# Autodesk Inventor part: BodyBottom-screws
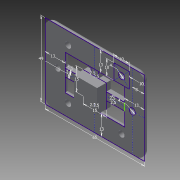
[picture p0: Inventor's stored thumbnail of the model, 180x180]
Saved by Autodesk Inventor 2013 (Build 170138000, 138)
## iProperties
Created: 2013-03
Part Number: BodyBottom-screws
Material: Generic
Document SubType Name: Modeling
Designer: frankenteddy
Density: 1 g/cm^3
Author: frankenteddy
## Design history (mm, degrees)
node "Blocks"
  sketch "Block1"
    geometry: L1 (49.279, 30.472)-(71.779, 30.472); L2 (71.779, 30.472)-(71.779, 18.072); L3 (71.779, 18.072)-(49.279, 18.072); L4 (49.279, 18.072)-(49.279, 30.472); L5 (49.279, 30.472)-(44.779, 30.472); L6 (44.779, 30.472)-(44.779, 18.072); L7 (44.779, 18.072)-(49.279, 18.072); L8 (49.279, 18.072)-(49.279, 30.472); L9 (71.779, 30.472)-(76.279, 30.472); L10 (76.279, 30.472)-(76.279, 18.072); L11 (76.279, 18.072)-(71.779, 18.072); L12 (71.779, 18.072)-(71.779, 30.472); L13 (44.779, 24.272)-(76.279, 24.272); L14 (60.529, 30.472)-(60.529, 18.072); L15 (47.029, 30.472)-(47.029, 18.072); L16 (74.029, 30.472)-(74.029, 18.072); C1 r 1.1 at (47.029, 24.272); C2 r 1.1 at (74.029, 24.272); 1 further point
    constraints: 32 end point, 8 midpoint, 6 parallel, 3 horizontal, 3 perpendicular, 2 centre point, 2 point on line
    dimensions: "d30" = 22.5 distance of L2.end L3.end; "d31" = 12.4 distance of L1.end L2.end; "d32" = 4.5 distance of L7.end L6.end; "d33" = 4.5 distance of L10.end L11.end; "d34" = 2.2 diameter of C1; "d35" = 2.2 diameter of C2; "d36" = 2.25 distance between parallel lines of L10 L16
sketch "Sketch1"
  geometry: L1 (-32.5, 24.5)-(32.5, 24.5); L2 (32.5, 24.5)-(32.5, -24.5); L3 (32.5, -24.5)-(-32.5, -24.5); L4 (-32.5, -24.5)-(-32.5, 24.5); L5 (-19.5, 11.5)-(19.5, 11.5); L6 (19.5, 11.5)-(19.5, -11.5); L7 (19.5, -11.5)-(-19.5, -11.5); L8 (-19.5, -11.5)-(-19.5, 11.5); L9 (-24.5, 24.5)-(-24.5, -24.5); L10 (-22.5, 11.5)-(-12.5, 11.5); L11 (-12.5, 11.5)-(-12.5, 21.5); L12 (-12.5, 21.5)-(-22.5, 21.5); L13 (-22.5, 21.5)-(-22.5, 11.5); L14 (-22.5, 21.5)-(-12.5, 11.5); L15 (-22.5, 11.5)-(-12.5, 21.5); L16 (32.5, 0)-(-32.5, 0); L17 (5.25, 11.5)-(-0.25, 11.5); L18 (-19.5, 2.5)-(-19.5, -2.5); L19 (5.25, -11.5)-(-0.25, -11.5); L20 (-7.5, 7.5)-(7.5, 7.5); L21 (7.5, 7.5)-(7.5, -7.5); L22 (7.5, -7.5)-(-7.5, -7.5); L23 (-7.5, -7.5)-(-7.5, 7.5); L24 (0, -7.5)-(0, 7.5); L25 (7.5, 0)-(-7.5, 0); L26 (0, 24.5)-(0, -24.5); L27 (7.5, 2.5)-(19.5, 2.5); L28 (7.5, -2.5)-(19.5, -2.5); L29 (2.5, 7.5)-(2.5, 11.5); L30 (-2.5, 7.5)-(-2.5, 11.5); L31 (-7.5, 2.5)-(-19.5, 2.5); L32 (-7.5, -2.5)-(-19.5, -2.5); L33 (-2.5, -7.5)-(-2.5, -11.5); L34 (2.5, -7.5)-(2.5, -11.5); C1 r 2 at (-24.5, 0); C2 r 2 at (-17.5, 16.5); 2 further points
  constraints: 68 end point, 17 point on line, 12 midpoint, 10 perpendicular, 9 parallel, 4 horizontal, 3 collinear, 2 centre point, 1 coincident, 1 horizontal alignment, 1 vertical alignment
  dimensions: "d0" = 65 distance of L2.end L3.end; "d1" = 49 distance of L1.end L2.end; "d2" = 13 distance between parallel lines of L5 L1; "d3" = 13 distance between parallel lines of L4 L8; "d4" = 13 distance between parallel lines of L3 L7; "d5" = 13 distance between parallel lines of L2 L6; "d11" = 8 distance between parallel lines of L9 L4; "d12" = 4 diameter of C1; "d20" = 10 distance of L12.end L11.end; "d21" = 10 distance of L11.end L10.end; "d23" = 4 diameter of C2; "d26" = 10 distance between parallel lines of L4 L13; "d71" = 15 distance of L21.end L22.end; "d72" = 15 distance of L20.end L21.end; "d73" = 2.5 distance between parallel lines of L27 L16; "d74" = 2.5 distance between parallel lines of L28 L16; "d75" = 2.5 distance between parallel lines of L26 L29; "d76" = 2.5 distance between parallel lines of L26 L30; "d77" = 2.5 distance between parallel lines of L26 L33; "d78" = 2.5 distance between parallel lines of L34 L26; "d79" = 2.5 distance between parallel lines of L16 L31; "d80" = 2.5 distance between parallel lines of L32 L16
extrude "Extrusion1" new body sketch "Sketch1" distance "d6" = 3; taper "d7" = 0 deg
extrude "Extrusion2" cut sketch "Sketch1" distance "d8" = 3; taper "d9" = 0 deg
extrude "Extrusion4" cut sketch "Sketch1" distance "d18" = 3; taper "d19" = 0 deg
mirror "Mirror1"
extrude "Extrusion5" cut sketch "Sketch1" distance "d24" = 3; taper "d25" = 0 deg
mirror "Mirror4"
mirror "Mirror5"
extrude "Extrusion14" join sketch "Sketch1" distance "d81" = 3; taper "d82" = 0 deg
fillet "Fillet1" dims "d27" = 5
fillet "Fillet2" dims "d28" = 2
fillet "Fillet4" dims "d65" = 2
extrude "Extrusion17" join sketch "Sketch1" distance "d105" = 6; taper "d106" = 0 deg
extrude "Extrusion16" join sketch "Sketch1" distance "d87" = 3; taper "d88" = 0 deg
sketch "Sketch6"
  geometry: L1 (0, 0)-(6.5, 0); L2 (0, 0)-(-6.5, 0); L3 (-6.5, 0)-(6.5, 0); L4 (6.5, 0)-(6.5, 3); L5 (6.5, 3)-(-6.5, 3); L6 (-6.5, 3)-(-6.5, 0); L7 (0, 3)-(0, 0); L8 (0, 5.75)-(0, -4.15); A1 r 4.95 centre (0, 0.8) between (0, 5.75) and (0, -4.15)
  constraints: 16 end point, 2 collinear, 2 horizontal, 2 parallel, 2 point on circle, 1 centre point, 1 midpoint, 1 perpendicular, 1 point on line
  dimensions: "d98" = 6.5 distance of L1.start L1.end; "d99" = 6.5 distance of L1.start L2.end; "d100" = 13 distance of L5.end L4.end; "d101" = 3 distance of L4.end L3.end; "d102" = 9.9 diameter of A1; "d103" = 2.2 distance from line of A1.centre L5
revolve "Revolution3" sketch "Sketch6" stored, may be unused: angle "d104" = 90 deg
body "Solid1"
